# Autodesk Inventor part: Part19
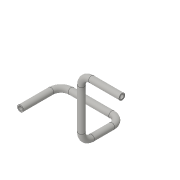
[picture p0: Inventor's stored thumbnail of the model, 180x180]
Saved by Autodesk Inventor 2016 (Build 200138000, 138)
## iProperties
Created: 2015-05
Part Number: Part19
Material: Generic
Document SubType Name: Modeling
Designer: Sandeep
Density: 1 g/cm^3
Appearance: Default
Author: Sandeep
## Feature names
1. Sweep1
## Parameters: d10 = 6 mm, d11 = 4 mm, d12 = 0, d13 = 0
